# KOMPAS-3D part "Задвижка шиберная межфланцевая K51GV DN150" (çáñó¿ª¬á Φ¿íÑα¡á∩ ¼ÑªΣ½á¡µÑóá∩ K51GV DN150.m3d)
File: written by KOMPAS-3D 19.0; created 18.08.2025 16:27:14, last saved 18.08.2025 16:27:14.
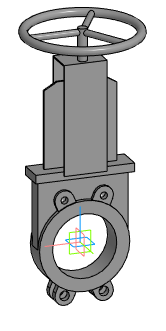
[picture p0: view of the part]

Document properties: Автор: Евгений; Полное имя файла: E:\Dendor Работа Сачек\3D для проектировщиков\2.4 Тип K51GV. Задвижка шиберная межфланцевая\stp_Задвижка шиберная K51GV DN50-400 с маховиком\Задвижка шиберная межфланцевая K51GV DN150.m3d

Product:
- Part/product: Задвижка шиберная межфланцевая K51GV DN150

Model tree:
1. Операция без истории:1  (labels: Задвижка шиберная межфланцевая K51GV DN150)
